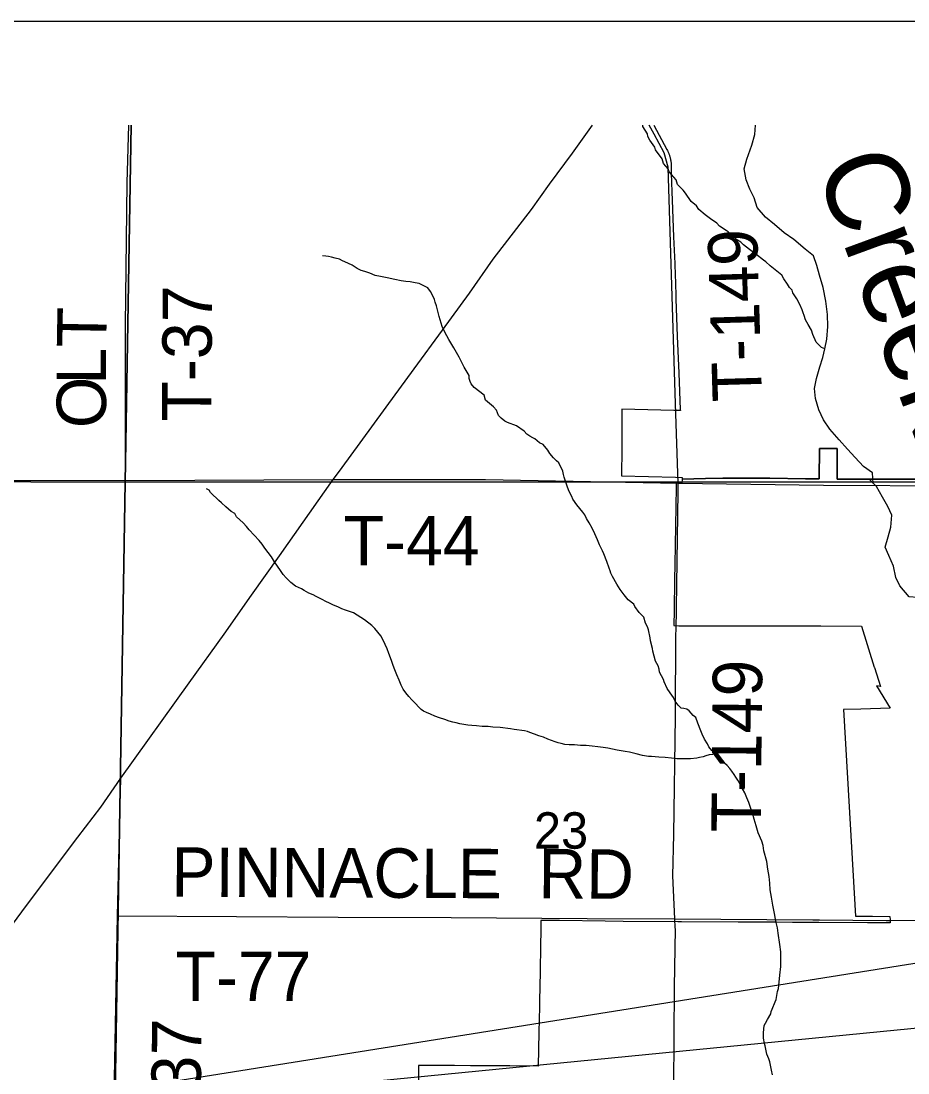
# Model space of a CAD drawing. Extents: x 0 to 34, y 0 to 22.
# Drawn here: x 3.924 to 4.944, y 16.112 to 17.321 of the extents above; entities that cross this region are included whole.
import ezdxf

# ---------------------------------------------------------------- set-up
doc = ezdxf.new("R2010")
doc.units = 0
for name, color, linetype in [('GM_X_County_Road', 7, 'Continuous'), ('GM_X_County_Road_Text', 7, 'Continuous'), ('GM_X_Interchange_Ramps', 7, 'Continuous'), ('GM_X_Minor_River', 7, 'Continuous'), ('GM_X_Minor_River_Text', 7, 'Continuous'), ('GM_X_Section', 7, 'Continuous'), ('GM_X_Section_Text', 7, 'Continuous'), ('GM_X_State_Route', 7, 'Continuous'), ('GM_X_Township_Road', 7, 'Continuous'), ('GM_X_Township_Road_Text', 7, 'Continuous'), ('SH_Data', 7, 'Continuous'), ('SH_Text', 7, 'Continuous')]:
    doc.layers.add(name, color=color, linetype=linetype)

msp = doc.modelspace()

# ---------------------------------------------------------------- linework, layer by layer
at = {"layer": 'GM_X_County_Road'}
for points in [[(2.1171, 16.7968), (2.2769, 16.7951), (2.4356, 16.7891), (2.5828, 16.7904), (2.6089, 16.7905), (2.664, 16.7909), (2.8237, 16.7904), (3.0081, 16.7905), (3.0639, 16.7903), (3.1192, 16.79), (3.3661, 16.7938), (3.6388, 16.7936), (4.0443, 16.793), (4.283, 16.7943)], [(4.0289, 15.9515), (4.0291, 15.9644), (4.0311, 16.0847), (4.0341, 16.2506), (4.035, 16.2928), (4.0387, 16.4512)]]:
    msp.add_lwpolyline(points, dxfattribs=at)
at = {"layer": 'GM_X_Interchange_Ramps'}
for points in [[(4.6517, 17.2013), (4.6667, 17.1734), (4.6673, 17.1723), (4.6676, 17.1717), (4.6679, 17.171), (4.6682, 17.1704), (4.6685, 17.1697), (4.6688, 17.169), (4.669, 17.1683), (4.6693, 17.1677), (4.6695, 17.167), (4.6697, 17.1663), (4.67, 17.1656), (4.6702, 17.1649), (4.6704, 17.1642), (4.6705, 17.1635), (4.6707, 17.1628), (4.6709, 17.1621), (4.671, 17.1614), (4.6712, 17.1604), (4.6712, 17.1599), (4.6713, 17.1592), (4.6714, 17.1585), (4.6715, 17.1578), (4.6716, 17.157), (4.6716, 17.1563), (4.6717, 17.1556), (4.6717, 17.1549), (4.6717, 17.1541), (4.6717, 17.1534), (4.6717, 17.1527), (4.6717, 17.1519), (4.6716, 17.1475), (4.6715, 17.1464), (4.6722, 17.1248), (4.6726, 17.1153), (4.6744, 17.0731), (4.6757, 17.0424), (4.6757, 17.0411), (4.6766, 17.0196), (4.6769, 17.0056), (4.6769, 17.0016), (4.6784, 16.9591), (4.6803, 16.9166), (4.6821, 16.8746), (4.6822, 16.8734), (4.6746, 16.8735), (4.615, 16.8749), (4.6147, 16.83), (4.6146, 16.7983), (4.6765, 16.7968), (4.6841, 16.7967), (4.6841, 16.7948), (4.7109, 16.7953), (4.7309, 16.7956), (4.7452, 16.7956), (4.785, 16.7956), (4.8262, 16.7951), (4.8342, 16.795), (4.8418, 16.7949), (4.842, 16.8299), (4.8579, 16.8299), (4.8626, 16.8298), (4.8626, 16.8224), (4.8624, 16.7948), (4.8669, 16.7948), (4.8814, 16.7947), (4.9101, 16.7946), (4.9136, 16.7945), (4.9178, 16.7945), (4.9245, 16.7945), (4.9656, 16.7946)], [(4.9656, 16.7946), (4.9245, 16.7945), (4.9178, 16.7945), (4.9136, 16.7945), (4.9101, 16.7946), (4.8814, 16.7947), (4.8669, 16.7948), (4.8624, 16.7948), (4.8626, 16.8224), (4.8626, 16.8298), (4.8579, 16.8299), (4.842, 16.8299), (4.8418, 16.7949), (4.8342, 16.795), (4.8262, 16.7951), (4.785, 16.7956), (4.7452, 16.7956), (4.7309, 16.7956), (4.7109, 16.7953), (4.6841, 16.7948), (4.684, 16.79), (4.6772, 16.79), (4.6772, 16.7855), (4.6759, 16.6964), (4.6756, 16.6795), (4.6751, 16.6439), (4.6748, 16.6263), (4.6805, 16.6262), (4.7259, 16.6262), (4.7317, 16.6262), (4.8024, 16.6261), (4.8127, 16.626), (4.8435, 16.626), (4.8905, 16.6259), (4.9051, 16.5786), (4.9053, 16.5781), (4.9122, 16.5562), (4.9078, 16.557), (4.9235, 16.5316), (4.8898, 16.5305), (4.8703, 16.5299), (4.8696, 16.5299), (4.8742, 16.4511), (4.8804, 16.3453), (4.8835, 16.2924), (4.8851, 16.2924), (4.903, 16.2923), (4.9227, 16.2922), (4.9231, 16.2922), (4.9233, 16.2883), (4.9235, 16.2847), (4.9229, 16.2847), (4.8974, 16.2848), (4.8412, 16.2851), (4.8111, 16.2853), (4.7927, 16.2854), (4.781, 16.2854), (4.7488, 16.2856), (4.6833, 16.2859), (4.6793, 16.286), (4.6165, 16.2865), (4.5956, 16.2867), (4.543, 16.2873), (4.5417, 16.2873), (4.5374, 16.2873), (4.5218, 16.2874), (4.5216, 16.2791), (4.5204, 16.2086), (4.5202, 16.1982), (4.52, 16.1881), (4.5195, 16.1591), (4.5191, 16.1397), (4.5188, 16.1202), (4.4861, 16.1204), (4.4619, 16.1205), (4.4417, 16.1206), (4.4408, 16.1206), (4.4224, 16.1207), (4.4121, 16.1208), (4.3812, 16.1209), (4.3805, 16.0788)]]:
    msp.add_lwpolyline(points, dxfattribs=at)
at = {"layer": 'GM_X_Minor_River'}
for points in [[(4.8483, 16.9444), (4.8444, 16.9459), (4.8385, 16.9522), (4.8345, 16.961), (4.8328, 16.966), (4.8291, 16.9722), (4.8262, 16.9776), (4.8244, 16.9826), (4.8234, 16.9857), (4.8223, 16.9891), (4.8194, 16.9953), (4.8161, 17.0018), (4.8114, 17.0088), (4.8107, 17.0119), (4.8077, 17.015), (4.8055, 17.0188), (4.8011, 17.0247), (4.7989, 17.0289), (4.7855, 17.0399), (4.7803, 17.0442), (4.7776, 17.0462), (4.7691, 17.0532), (4.7616, 17.0587), (4.7549, 17.0639), (4.7515, 17.067), (4.7459, 17.0706), (4.7452, 17.0732), (4.7418, 17.0748), (4.7373, 17.0788), (4.7347, 17.0803), (4.7272, 17.0855), (4.7242, 17.089), (4.7167, 17.0937), (4.7108, 17.0984), (4.7033, 17.1047), (4.7007, 17.1086), (4.6944, 17.1137), (4.6882, 17.1234), (4.6852, 17.1269), (4.6789, 17.1331), (4.6775, 17.1385), (4.6693, 17.1478), (4.6683, 17.1513), (4.6627, 17.1575), (4.6613, 17.1628), (4.6536, 17.1729), (4.6529, 17.176), (4.647, 17.1841), (4.6448, 17.1884), (4.6445, 17.1914), (4.639, 17.1999), (4.6389, 17.2013)], [(4.904, 16.7898), (4.903, 16.8018), (4.8929, 16.8093), (4.8833, 16.8195), (4.8745, 16.8292), (4.8648, 16.8398), (4.8542, 16.8522), (4.8468, 16.8627), (4.8414, 16.8743), (4.8376, 16.8873), (4.8364, 16.8987), (4.8386, 16.9105), (4.8424, 16.9237), (4.8461, 16.9346), (4.8483, 16.9444), (4.8505, 16.9554), (4.8517, 16.9702), (4.8513, 16.9839), (4.8494, 16.9991), (4.8464, 17.0148), (4.8422, 17.029), (4.8391, 17.0401), (4.8352, 17.0512), (4.8255, 17.0591), (4.8125, 17.0701), (4.8017, 17.0777), (4.7905, 17.0871), (4.7801, 17.0957), (4.7705, 17.1067), (4.767, 17.1178), (4.7619, 17.1278), (4.7577, 17.1386), (4.7557, 17.1512), (4.7587, 17.1625), (4.7645, 17.1783), (4.7678, 17.1908), (4.7685, 17.2013)], [(4.509, 16.844), (4.5056, 16.8463), (4.5027, 16.8498), (4.4937, 16.8561), (4.4835, 16.8598), (4.4805, 16.8614), (4.476, 16.8646), (4.473, 16.8677), (4.4709, 16.8738), (4.4672, 16.8777), (4.4582, 16.8856), (4.4565, 16.8913), (4.4449, 16.9), (4.4416, 16.9042), (4.4405, 16.9069), (4.4394, 16.9104), (4.4392, 16.9138), (4.4337, 16.9235), (4.4279, 16.9347), (4.4217, 16.9455), (4.4158, 16.9551), (4.4115, 16.9636), (4.4082, 16.9702), (4.4047, 16.9817), (4.4033, 16.9878), (4.4016, 16.9939), (4.4002, 16.9982), (4.3995, 17.0012), (4.3984, 17.0039), (4.3948, 17.0101), (4.3918, 17.0144), (4.3817, 17.0196), (4.3771, 17.0204), (4.3714, 17.0213), (4.3665, 17.0218), (4.3611, 17.0227), (4.3539, 17.024), (4.3452, 17.0261), (4.3373, 17.0275), (4.3312, 17.0288), (4.3252, 17.0312), (4.3195, 17.0332), (4.3153, 17.0345), (4.3104, 17.0369), (4.3048, 17.0405), (4.2965, 17.0445), (4.2935, 17.0457), (4.2901, 17.0473), (4.2852, 17.0485), (4.281, 17.0498), (4.2776, 17.0506), (4.2746, 17.0507), (4.2708, 17.0512)], [(4.7828, 16.3463), (4.7815, 16.3551), (4.778, 16.3677), (4.7774, 16.3738), (4.7757, 16.3788), (4.7717, 16.3881), (4.7692, 16.3961), (4.7671, 16.4038), (4.765, 16.4107), (4.7629, 16.4172), (4.7608, 16.423), (4.7586, 16.4284), (4.7561, 16.4342), (4.7536, 16.4388), (4.7518, 16.4427), (4.7481, 16.4488), (4.7459, 16.4523), (4.7441, 16.4554), (4.7415, 16.4589), (4.7389, 16.462), (4.736, 16.4655), (4.733, 16.4683), (4.7304, 16.4714), (4.7274, 16.4749), (4.7237, 16.4788), (4.7185, 16.4827), (4.7148, 16.487), (4.7134, 16.4905), (4.7101, 16.4959), (4.7072, 16.5016), (4.7057, 16.5055), (4.7022, 16.5143), (4.7, 16.5209), (4.697, 16.5232), (4.6944, 16.5256), (4.6922, 16.5283), (4.6896, 16.5303), (4.6862, 16.5311), (4.6832, 16.5316), (4.6798, 16.5351), (4.6761, 16.5394), (4.6743, 16.5436), (4.6706, 16.549), (4.667, 16.5541), (4.6634, 16.5618), (4.6627, 16.5644), (4.6583, 16.5729), (4.6576, 16.5764), (4.6566, 16.5802), (4.6537, 16.5856), (4.6505, 16.5971), (4.6502, 16.6002), (4.6478, 16.609), (4.6475, 16.6124), (4.6455, 16.6216), (4.6444, 16.6251), (4.6422, 16.6293), (4.6401, 16.6362), (4.6349, 16.6413), (4.6298, 16.6483), (4.6287, 16.651), (4.6223, 16.6561), (4.6175, 16.6619), (4.6131, 16.6677), (4.6091, 16.6739), (4.604, 16.6828), (4.6022, 16.6867), (4.6015, 16.6894), (4.6004, 16.6924), (4.5975, 16.7001), (4.5943, 16.709), (4.5925, 16.7124), (4.5893, 16.719), (4.5868, 16.7251), (4.5839, 16.7317), (4.5806, 16.7382), (4.5773, 16.7444), (4.5744, 16.7494), (4.5722, 16.7537), (4.57, 16.7568), (4.5667, 16.761), (4.563, 16.7653), (4.5586, 16.7715), (4.5572, 16.7746), (4.5553, 16.7781), (4.5535, 16.7823), (4.5521, 16.7865), (4.5503, 16.7912), (4.5486, 16.7969), (4.5479, 16.8), (4.5469, 16.8038), (4.5425, 16.8134), (4.5399, 16.8158), (4.5362, 16.8193), (4.5321, 16.824), (4.5296, 16.8278), (4.5244, 16.8344), (4.5203, 16.8364), (4.515, 16.8411), (4.5124, 16.8423), (4.509, 16.844)], [(4.9854, 16.6035), (4.9856, 16.6063), (4.9856, 16.6192), (4.9844, 16.6322), (4.9813, 16.6437), (4.9786, 16.6556), (4.9755, 16.6678), (4.9651, 16.6655), (4.9547, 16.6585), (4.9452, 16.6595), (4.9345, 16.672), (4.9298, 16.6817), (4.9271, 16.6947), (4.9217, 16.707), (4.9178, 16.7166), (4.9212, 16.7283), (4.9242, 16.7396), (4.9253, 16.7533), (4.9206, 16.7633), (4.9144, 16.7741), (4.9075, 16.7861), (4.9001, 16.7939)], [(4.2156, 16.6998), (4.2119, 16.7052), (4.2045, 16.7153), (4.2012, 16.72), (4.1979, 16.7242), (4.1864, 16.7363), (4.1831, 16.7402), (4.1794, 16.7445), (4.1719, 16.7512), (4.1697, 16.755), (4.1656, 16.7574), (4.1596, 16.7629), (4.1544, 16.7676), (4.1514, 16.7703), (4.1488, 16.7727), (4.1451, 16.7762), (4.1418, 16.7793), (4.1403, 16.782), (4.1373, 16.7836)], [(4.7237, 16.4788), (4.7153, 16.4778), (4.7115, 16.4768), (4.7084, 16.4757), (4.7042, 16.4747), (4.7011, 16.474), (4.6939, 16.4734), (4.6881, 16.4732), (4.6782, 16.4734), (4.6721, 16.4739), (4.6645, 16.4749), (4.6573, 16.475), (4.6489, 16.476), (4.6455, 16.4761), (4.6387, 16.477), (4.6315, 16.4791), (4.6235, 16.4808), (4.6186, 16.4817), (4.6095, 16.4834), (4.6042, 16.4843), (4.5989, 16.4856), (4.5932, 16.4861), (4.5871, 16.487), (4.5806, 16.4879), (4.5738, 16.4885), (4.5673, 16.4886), (4.5605, 16.4892), (4.5544, 16.4893), (4.5494, 16.4898), (4.5452, 16.4907), (4.5415, 16.4916), (4.5381, 16.4928), (4.5298, 16.496), (4.5249, 16.498), (4.5196, 16.4997), (4.5143, 16.5017), (4.509, 16.5034), (4.5063, 16.5046), (4.5029, 16.5054), (4.4912, 16.5069), (4.487, 16.5077), (4.4748, 16.5092), (4.4664, 16.5097), (4.4611, 16.5103), (4.4543, 16.5104), (4.4478, 16.511), (4.4425, 16.5115), (4.4379, 16.512), (4.433, 16.5128), (4.4284, 16.5133), (4.4243, 16.5146), (4.4205, 16.5154), (4.4163, 16.5167), (4.4114, 16.5183), (4.4053, 16.5204), (4.3997, 16.5224), (4.3948, 16.5244), (4.3903, 16.5264), (4.3869, 16.5281), (4.3843, 16.53), (4.3813, 16.5328), (4.3776, 16.537), (4.3735, 16.5409), (4.3698, 16.5448), (4.3664, 16.5491), (4.3635, 16.5534), (4.3613, 16.558), (4.3588, 16.5638), (4.3563, 16.5699), (4.3538, 16.5757), (4.352, 16.5807), (4.3502, 16.5853), (4.3488, 16.5895), (4.347, 16.5942), (4.3449, 16.5995), (4.3406, 16.6096), (4.3376, 16.6146), (4.331, 16.6231), (4.3273, 16.6266), (4.3191, 16.6329), (4.3149, 16.6357), (4.3104, 16.6385), (4.3063, 16.6409), (4.2972, 16.6441), (4.2927, 16.6458), (4.2882, 16.6478), (4.2833, 16.6498), (4.2788, 16.6522), (4.2746, 16.6542), (4.2701, 16.6562), (4.2633, 16.6598), (4.26, 16.6618), (4.255, 16.6638), (4.2494, 16.6666), (4.2464, 16.6686), (4.2396, 16.6718), (4.2344, 16.6757), (4.2288, 16.6812), (4.2255, 16.6851), (4.2222, 16.6897), (4.2156, 16.6998)], [(4.7881, 16.1102), (4.7871, 16.1156), (4.7851, 16.1252), (4.7837, 16.1286), (4.7815, 16.134), (4.7795, 16.1436), (4.7788, 16.1463), (4.7778, 16.1524), (4.7779, 16.1554), (4.7776, 16.1585), (4.7786, 16.1669), (4.7802, 16.1695), (4.7825, 16.1736), (4.7861, 16.1804), (4.7866, 16.1831), (4.7878, 16.1857), (4.7911, 16.194), (4.7923, 16.1966), (4.794, 16.2058), (4.7949, 16.2095), (4.7959, 16.2168), (4.7964, 16.2247), (4.7975, 16.2346), (4.7977, 16.2434), (4.7975, 16.2514), (4.7966, 16.2598), (4.7946, 16.2728), (4.7937, 16.2789), (4.7919, 16.2866), (4.7903, 16.2954), (4.7886, 16.305), (4.7869, 16.3142), (4.7856, 16.3226), (4.7851, 16.3302), (4.7841, 16.3382), (4.7828, 16.3463)]]:
    msp.add_lwpolyline(points, dxfattribs=at)
at = {"layer": 'GM_X_Section'}
for points in [[(4.0506, 17.2013), (4.0439, 16.7912), (3.0664, 16.7946), (3.0714, 17.2013)], [(5.0842, 17.2013), (5.0741, 16.7917), (4.0439, 16.7912), (4.0506, 17.2013)]]:
    msp.add_lwpolyline(points, dxfattribs=at)
for points in [[(3.0664, 16.7946), (4.0439, 16.7912), (4.0274, 15.7833), (3.0481, 15.7894)], [(4.0439, 16.7912), (5.0741, 16.7917), (5.0286, 15.7742), (4.0274, 15.7833)]]:
    msp.add_lwpolyline(points, close=True, dxfattribs=at)
at = {"layer": 'GM_X_State_Route'}
for points in [[(4.289, 16.8024), (4.3005, 16.8179), (4.3437, 16.8775), (4.3761, 16.9214), (4.4087, 16.9657), (4.4397, 17.0082), (4.467, 17.0476), (4.5108, 17.1045), (4.5317, 17.1338), (4.558, 17.1692), (4.5813, 17.2013)], [(4.0387, 16.4512), (4.1175, 16.5605), (4.1576, 16.6167), (4.1892, 16.6613), (4.2212, 16.7064), (4.283, 16.7943), (4.289, 16.8024)], [(3.5622, 15.8032), (3.5711, 15.8155), (3.5884, 15.84), (3.6326, 15.9018), (3.6726, 15.9555), (3.7225, 16.0236), (3.7496, 16.0602), (3.7945, 16.1214), (3.8283, 16.1669), (3.8734, 16.2283), (3.9291, 16.3031), (3.9895, 16.3833), (4.0157, 16.4179), (4.0387, 16.4512)]]:
    msp.add_lwpolyline(points, dxfattribs=at)
at = {"layer": 'GM_X_Township_Road'}
for p, q in [((4.6796, 16.7902), (4.6767, 16.8812)), ((4.6772, 16.6202), (4.6795, 16.7802)), ((4.6795, 16.7802), (4.6796, 16.7902)), ((4.6758, 16.2893), (4.8343, 16.2883)), ((4.6763, 16.2796), (4.6758, 16.2893))]:
    msp.add_line(p, q, dxfattribs=at)
for points in [[(4.0443, 16.793), (4.0443, 16.9715), (4.046, 17.1353), (4.0479, 17.2013)], [(4.6767, 16.8812), (4.668, 17.1532), (4.6635, 17.1698), (4.652, 17.1909), (4.6464, 17.2013)], [(4.283, 16.7943), (4.458, 16.7941), (4.6796, 16.7902)], [(4.6796, 16.7902), (4.8466, 16.7876), (4.9997, 16.7868), (5.027, 16.7864), (5.0372, 16.7835), (5.0418, 16.7723), (5.0496, 16.7383), (5.0548, 16.7297), (5.0678, 16.7267), (5.1454, 16.7273), (5.231, 16.7259), (5.2989, 16.7257)], [(4.6758, 16.2893), (4.6735, 16.339), (4.6746, 16.3865), (4.6766, 16.5218), (4.6771, 16.6172), (4.6772, 16.6202)], [(4.035, 16.2928), (4.1717, 16.2921), (4.2885, 16.2913), (4.4187, 16.2908), (4.5751, 16.2898), (4.6758, 16.2893)], [(4.8343, 16.2883), (4.8422, 16.2882), (4.9187, 16.2873), (4.9236, 16.2874)], [(4.9236, 16.2874), (5.0163, 16.2882), (5.0616, 16.2888), (5.1068, 16.2886), (5.1909, 16.287)], [(4.8221, 15.7638), (4.8184, 15.7715), (4.8079, 15.7748), (4.6675, 15.7752), (4.6653, 15.79), (4.6638, 15.8041), (4.6727, 15.9738), (4.6746, 16.0964), (4.6756, 16.2113), (4.6765, 16.2777), (4.6763, 16.2796)]]:
    msp.add_lwpolyline(points, dxfattribs=at)
at = {"layer": 'SH_Data'}
msp.add_line((2, 17.3211), (9, 17.3211), dxfattribs=at)
at = {"layer": 'SH_Text'}
msp.add_lwpolyline([(9.6169, 16.9806), (3.7384, 16.0451), (9.6169, 16.6206)], close=True, dxfattribs=at)

# ---------------------------------------------------------------- texts
at = {"layer": 'GM_X_County_Road_Text'}
msp.add_text('C-37', height=0.05682, rotation=89.3142, dxfattribs=at).set_placement((4.1296, 16.0096))
at = {"layer": 'GM_X_Minor_River_Text'}
msp.add_text('Creek', height=0.0947, rotation=290.1517, dxfattribs=at).set_placement((4.8369, 17.1541))
at = {"layer": 'GM_X_Section_Text'}
msp.add_text('23', height=0.04186, rotation=0, dxfattribs=at).set_placement((4.5138, 16.37))
at = {"layer": 'GM_X_Township_Road_Text'}
for s, height, rotation, p in [('T-149', 0.05682, 91.6849, (4.7761, 16.8845)), ('T-37', 0.05682, 89.6638, (4.1428, 16.8607)), ('T', 0.0568, 89.0228, (4.0219, 16.9455)), ('L', 0.0568, 89.9571, (4.0218, 16.9033)), ('O', 0.0568, 90, (4.0218, 16.8533)), ('T-44', 0.05682, 0, (4.295, 16.6955)), ('T-149', 0.05682, 89.4406, (4.7745, 16.3884)), ('PINNACLE', 0.05682, 359.7221, (4.0968, 16.3148)), ('RD', 0.05682, 359.5054, (4.5188, 16.3131)), ('T-77', 0.05682, 0, (4.1017, 16.1948))]:
    msp.add_text(s, height=height, rotation=rotation, dxfattribs=at).set_placement(p)

doc.saveas('drawing.dxf')
